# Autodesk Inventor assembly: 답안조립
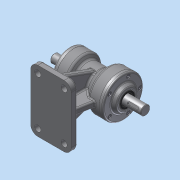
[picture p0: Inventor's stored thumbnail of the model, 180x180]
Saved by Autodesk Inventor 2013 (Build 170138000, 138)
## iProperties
Created: 2015-08
Part Number: 답안조립
Document SubType Name: Assembly
Designer: WINDOWS7
Author: WINDOWS7
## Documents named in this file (10)
- C:\Users\WINDOWS7\Desktop\450806V1031\답안조립.iam
- C:\Users\WINDOWS7\Desktop\450806V1031\M4x0.5.ipt
- C:\Users\WINDOWS7\Desktop\450806V1031\뒤커버.ipt
- C:\Users\WINDOWS7\Desktop\450806V1031\베어링 6203.ipt
- C:\Users\WINDOWS7\Desktop\450806V1031\베어링 6205.ipt
- C:\Users\WINDOWS7\Desktop\450806V1031\본체.ipt
- C:\Users\WINDOWS7\Desktop\450806V1031\앞커버.ipt
- C:\Users\WINDOWS7\Desktop\450806V1031\오일실 .ipt
- 오일실 .ipt
- C:\Users\WINDOWS7\Desktop\450806V1031\축.ipt
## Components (10 placed, 1 different names)
1. M4x0.5:1
2. M4x0.5:3
3. M4x0.5:4
4. M4x0.5:5
5. M4x0.5:6
6. M4x0.5:2
7. M4x0.5:7
8. M4x0.5:8
9. M4x0.5:9
10. M4x0.5:10
